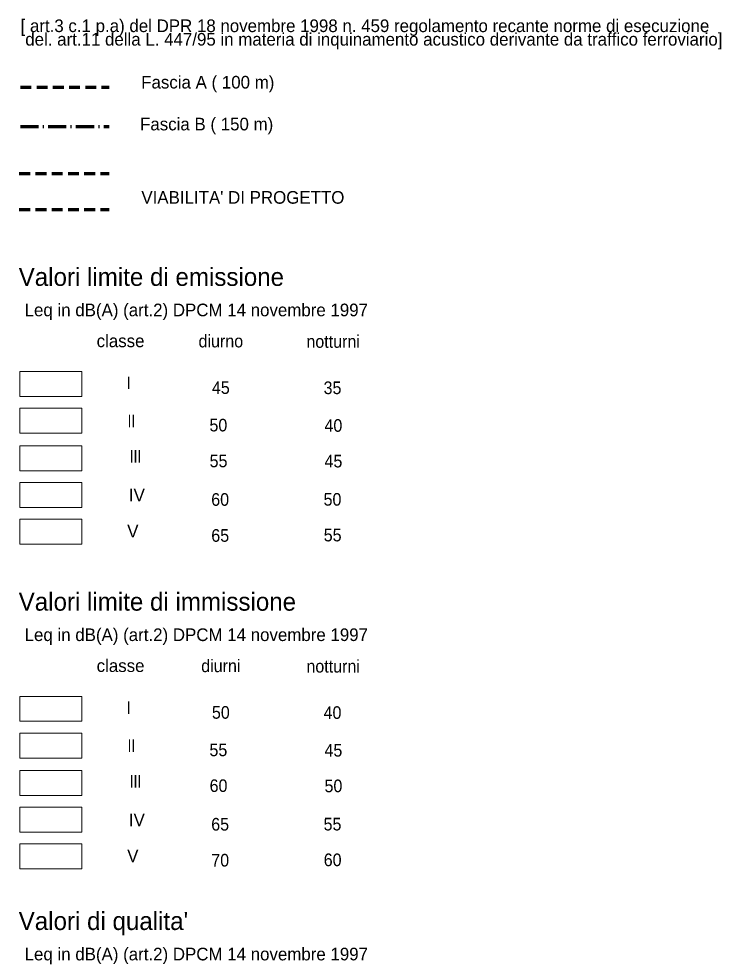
# Model space of a CAD drawing. Extents: x 654952 to 658955, y 890426 to 894481.
# Drawn here: x 656069 to 656849, y 892344 to 893386 of the extents above; entities that cross this region are included whole.
import ezdxf
from ezdxf.enums import TextEntityAlignment as Align

# ---------------------------------------------------------------- set-up
doc = ezdxf.new("R2010")
doc.units = 0
doc.header["$LTSCALE"] = 4
doc.linetypes.add('DOT_DASHED', pattern=[7.7, 5, -1.2, 0.3, -1.2])
doc.linetypes.add('MEDIUM_DASHED', pattern=[4.5, 3, -1.5])
doc.layers.add('60', color=7, linetype='Continuous', lineweight=35)

msp = doc.modelspace()

# ---------------------------------------------------------------- linework, layer by layer
at = {"layer": '60', "linetype": 'MEDIUM_DASHED', "lineweight": 70}
for p, q in [((656071.32, 893310.06), (656169.74, 893310.06)), ((656070.06, 893214.07), (656169.74, 893214.07)), ((656070.06, 893174.07), (656169.74, 893174.07))]:
    msp.add_line(p, q, dxfattribs=at)
at = {"layer": '60', "linetype": 'DOT_DASHED', "lineweight": 70}
msp.add_line((656071.32, 893266.34), (656169.74, 893266.34), dxfattribs=at)
at = {"layer": '60', "lineweight": 13}
for points in [[(656070.74, 892994.47), (656139.28, 892994.47), (656139.28, 892966.75), (656070.74, 892966.75)], [(656070.74, 892953.77), (656139.28, 892953.77), (656139.28, 892926.05), (656070.74, 892926.05)], [(656070.74, 892912.19), (656139.28, 892912.19), (656139.28, 892884.47), (656070.74, 892884.47)], [(656070.74, 892871.47), (656139.28, 892871.47), (656139.28, 892843.75), (656070.74, 892843.75)], [(656070.74, 892830.75), (656139.28, 892830.75), (656139.28, 892803.03), (656070.74, 892803.03)], [(656070.74, 892634.21), (656139.28, 892634.21), (656139.28, 892606.49), (656070.74, 892606.49)], [(656070.74, 892593.51), (656139.28, 892593.51), (656139.28, 892565.79), (656070.74, 892565.79)], [(656070.74, 892551.93), (656139.28, 892551.93), (656139.28, 892524.21), (656070.74, 892524.21)], [(656070.74, 892511.21), (656139.28, 892511.21), (656139.28, 892483.49), (656070.74, 892483.49)], [(656070.74, 892470.49), (656139.28, 892470.49), (656139.28, 892442.77), (656070.74, 892442.77)]]:
    msp.add_lwpolyline(points, close=True, dxfattribs=at)

# ---------------------------------------------------------------- texts
at = {"layer": '60'}
for s, height, p in [('[ art.3 c.1 p.a) del DPR 18 novembre 1998 n. 459 regolamento recante norme di esecuzione', 14, (656071.45, 893371.05)), (' del. art.11 della L. 447/95 in materia di inquinamento acustico derivante da traffico ferroviario]', 14, (656071.45, 893356.05)), ('Fascia A ( 100 m)', 14, (656205.23, 893308.44)), ('Fascia B ( 150 m)', 14, (656203.98, 893262.01)), ("VIABILITA' DI PROGETTO", 14, (656205.45, 893180.66)), ('Valori limite di emissione', 20, (656069.36, 893089.5)), ('Leq in dB(A) (art.2) DPCM 14 novembre 1997', 14, (656075.94, 893055.82)), ('Valori limite di immissione', 20, (656069.36, 892729.24)), ('Leq in dB(A) (art.2) DPCM 14 novembre 1997', 14, (656075.94, 892695.56)), ("Valori di qualita'", 20, (656069.36, 892375.02)), ('Leq in dB(A) (art.2) DPCM 14 novembre 1997', 14, (656075.94, 892341.34))]:
    msp.add_text(s, height=height, dxfattribs=at).set_placement(p)
for s, p in [('classe', (656182.35, 893021.5)), ('I', (656191.37, 892974.97)), ('IV', (656200.45, 892850.41)), ('V', (656195.96, 892810.47)), ('classe', (656182.35, 892661.24)), ('I', (656191.37, 892614.71)), ('IV', (656200.45, 892490.15)), ('V', (656195.96, 892450.21))]:
    msp.add_text(s, height=14, dxfattribs=at).set_placement(p, align=Align.CENTER)
for s, width, p in [('diurno', 0.95, (656293.57, 893021.3)), ('notturni', 0.95, (656418.13, 893020.86)), ('45', 0.95, (656293.57, 892969.64)), ('35', 0.95, (656417.42, 892969.46)), ('II', 0.8, (656194.31, 892932.65)), (' 50', 0.95, (656288.36, 892928.1)), ('40', 0.95, (656418.4, 892927.66)), ('III', 0.85, (656198.92, 892893.35)), (' 55', 0.95, (656288.54, 892888.38)), ('45', 0.95, (656418.44, 892888.12)), ('60', 0.95, (656292.81, 892845.58)), ('50', 0.95, (656417.4, 892845.72)), ('65', 0.95, (656292.88, 892805.68)), ('55', 0.95, (656417.57, 892806.1)), ('diurni', 0.95, (656293.56, 892661.04)), ('notturni', 0.95, (656418.13, 892660.6)), ('50', 0.95, (656293.57, 892609.38)), ('40', 0.95, (656417.42, 892609.2)), ('II', 0.8, (656194.31, 892572.39)), (' 55', 0.95, (656288.36, 892567.84)), ('45', 0.95, (656418.4, 892567.4)), ('III', 0.85, (656198.92, 892533.09)), (' 60', 0.95, (656288.54, 892528.12)), ('50', 0.95, (656418.44, 892527.86)), ('65', 0.95, (656292.81, 892485.32)), ('55', 0.95, (656417.4, 892485.46)), ('70', 0.95, (656292.88, 892445.42)), ('60', 0.95, (656417.57, 892445.84))]:
    msp.add_text(s, height=14, dxfattribs=dict(at, width=width)).set_placement(p, align=Align.CENTER)

doc.saveas('drawing.dxf')
